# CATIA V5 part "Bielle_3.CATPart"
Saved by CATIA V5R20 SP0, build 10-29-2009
Part number: Bielle_3
Bounding box of the stored display mesh (mm): x 0 to 1, y 8 to 12, z 18 to 47
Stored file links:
  C:\Users\J\IAO_2012_jgossard\Bielle_3.CATPart
  C:\Users\J\IAO_2012_jgossard\jgossard.CATProduct
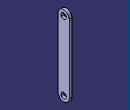
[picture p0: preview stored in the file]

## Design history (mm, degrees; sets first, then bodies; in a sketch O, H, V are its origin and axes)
Set1
  Plane1 "Plan_ref": linked copy from another document
  Point1 "Point_B": linked copy from another document
  Point2 "Point_C": linked copy from another document
Body1 (main body)
  Sketch1 on Plane1, origin (0, 0, 0), H (0, 1, 0), V (0, 0, 1)
    construction line L1 (10, 20) -> (10, 45)
    point P1 (10, 20)
    point P2 (10, 45)
    line L2 (8, 20) -> (8, 45)
    line L3 (12, 45) -> (12, 20)
    arc A1 centre (10, 45) radius 2 from (8, 45) to (12, 45) cw
    arc A2 centre (10, 20) radius 2 from (12, 20) to (8, 20) cw
    reference projected point E1 (10, 20) from Point1
    reference projected point E2 (10, 45) from Point2
    distance L1 L2 = 2
    vertical: L1 V
    tangency: A1 L2, A2 L2, A1 L3, A2 L3
    coincidence: P1 E1, P2 E2
  Pad1: profile Sketch1, direction (1, 0, 0), length 1
  Sketch2 on start face of Pad1, origin (0, 9.0766, 22.0167), H (0, -1, 0), V (0, 0, 1)
    point P1 (-0.9234, -2.0167)
    reference projected point E1 (-0.9234, -2.0167) from Point1
    coincidence: P1 E1
  Hole1: placed by Sketch2, at (0, 10, 20) direction (1, 0, 0), diameter 2, depth 10
  Sketch3 on start face of Pad1, origin (0, 11.2766, 31.358), H (0, -1, 0), V (0, 0, 1)
    point P1 (1.2766, 13.642)
    reference projected point E1 (1.2766, 13.642) from Point2
    coincidence: P1 E1
  Hole2: placed by Sketch3, at (0, 10, 45) direction (1, 0, 0), diameter 2, through (limit type 6)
